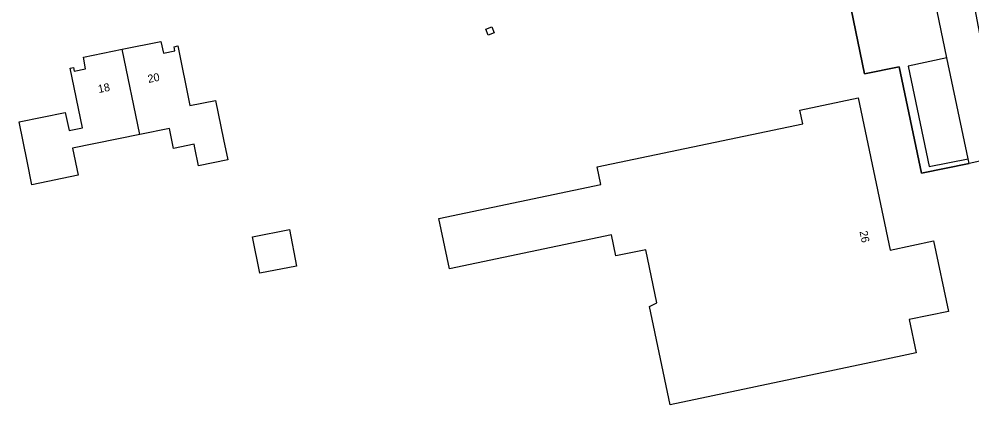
# Model space of a CAD drawing. Extents: x 164494 to 166241, y 382475 to 384494.
# Drawn here: x 164812.2 to 164931.2, y 384254.1 to 384302.2 of the extents above; entities that cross this region are included whole.
import ezdxf

# ---------------------------------------------------------------- set-up
doc = ezdxf.new("R2010")
doc.units = 0
for name, color, linetype in [('IMGEO_Groenvoorziening', 7, 'Continuous'), ('IMGEO_Hek', 7, 'Continuous'), ('IMGEO_Hoogspanningsmast', 7, 'Continuous'), ('IMGEO_Pand', 7, 'Continuous'), ('IMGEO_Pand_nummerreeks', 7, 'Continuous'), ('IMGEO_Parkeervlak_open', 7, 'Continuous'), ('IMGEO_Rijbaan_lokaal_open', 7, 'Continuous')]:
    doc.layers.add(name, color=color, linetype=linetype)

msp = doc.modelspace()

# ---------------------------------------------------------------- linework, layer by layer
at = {"layer": 'IMGEO_Groenvoorziening'}
msp.add_lwpolyline([(164930.87, 384284.21), (164924.88, 384283.02), (164922.1, 384296.28), (164917.77, 384295.38), (164913.08, 384318.23)], dxfattribs=at)
at = {"layer": 'IMGEO_Hek'}
for points in [[(164913.08, 384318.23), (164917.77, 384295.38)], [(164917.77, 384295.38), (164922.1, 384296.28), (164924.88, 384283.02), (164930.87, 384284.21)]]:
    msp.add_lwpolyline(points, dxfattribs=at)
at = {"layer": 'IMGEO_Hoogspanningsmast'}
msp.add_lwpolyline([(164870.78, 384300.23), (164870.49, 384300.98), (164871.23, 384301.26), (164871.52, 384300.51), (164870.78, 384300.23)], dxfattribs=at)
at = {"layer": 'IMGEO_Pand'}
for points in [[(164825.07, 384298.46), (164829.92, 384299.44), (164830.22, 384297.97), (164831.67, 384298.26), (164831.56, 384298.78), (164832.02, 384298.87), (164833.53, 384291.43), (164836.75, 384292.08), (164837.75, 384287.18), (164838.26, 384284.66), (164834.61, 384283.92), (164834.16, 384286.16), (164834.07, 384286.6), (164831.48, 384286.08), (164830.98, 384288.57), (164827.29, 384287.82)], [(164827.29, 384287.82), (164818.89, 384286.12), (164819.58, 384282.74), (164813.79, 384281.56), (164813.2, 384284.5), (164812.2, 384289.4), (164817.98, 384290.58), (164818.44, 384288.31), (164820.11, 384288.65), (164818.59, 384296.12), (164818.98, 384296.2), (164819.08, 384295.71), (164820.52, 384296), (164820.23, 384297.47), (164825.07, 384298.46)], [(164827.29, 384287.82), (164825.07, 384298.46)], [(164919.36, 384259.53), (164893.52, 384254.08), (164890.92, 384266.36), (164891.85, 384266.82), (164890.46, 384273.45), (164886.73, 384272.67), (164886.18, 384275.3), (164865.95, 384271.06), (164864.63, 384277.34), (164884.86, 384281.58), (164884.4, 384283.79), (164910.08, 384289.17), (164909.72, 384290.87), (164917, 384292.4), (164920.98, 384273.41), (164926.4, 384274.55), (164928.26, 384265.75), (164923.37, 384264.72), (164924.25, 384260.56), (164919.36, 384259.53)], [(164846.85, 384271.41), (164842.26, 384270.51), (164841.37, 384275.05), (164845.96, 384275.95), (164846.85, 384271.41)]]:
    msp.add_lwpolyline(points, dxfattribs=at)
at = {"layer": 'IMGEO_Parkeervlak_open'}
msp.add_lwpolyline([(164928.08, 384297.39), (164923.23, 384296.37), (164925.86, 384283.83), (164930.74, 384284.8)], dxfattribs=at)
at = {"layer": 'IMGEO_Rijbaan_lokaal_open'}
for points in [[(164931.6, 384329.7), (164931.19, 384325.23), (164929.57, 384322.57), (164928.46, 384318.74), (164931.19, 384305.52), (164935.03, 384285.1), (164930.87, 384284.21)], [(164928.08, 384297.39), (164923.54, 384319.3), (164914.8, 384323.85)], [(164930.74, 384284.8), (164928.08, 384297.39)], [(164930.87, 384284.21), (164930.74, 384284.8)]]:
    msp.add_lwpolyline(points, dxfattribs=at)

# ---------------------------------------------------------------- texts
at = {"layer": 'IMGEO_Pand_nummerreeks'}
for s, rotation, p in [('20', 11.4631, (164828.37, 384294.25)), ('18', 11.4631, (164822.16, 384292.99)), ('26', 281.8404, (164917.15, 384275.71))]:
    msp.add_text(s, height=1, rotation=rotation, dxfattribs=at).set_placement(p)

doc.saveas('drawing.dxf')
